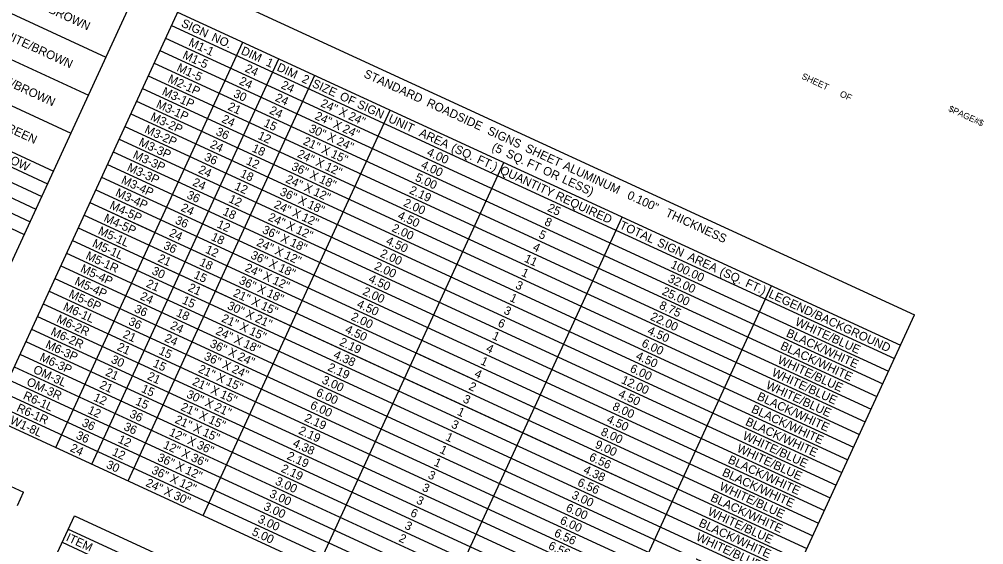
# Model space of a CAD drawing. Extents: x 627405 to 651306, y 367647 to 373430.
# Drawn here: x 650630 to 651306, y 372714 to 373082 of the extents above; entities that cross this region are included whole.
import ezdxf

# ---------------------------------------------------------------- set-up
doc = ezdxf.new("R2010")
doc.units = 0
for name, color, linetype in [('Default', 7, 'Continuous'), ('R_Border', 7, 'Continuous'), ('R_Dimension', 7, 'Continuous'), ('R_No Plot', 7, 'Continuous')]:
    doc.layers.add(name, color=color, linetype=linetype)

msp = doc.modelspace()

# ---------------------------------------------------------------- linework, layer by layer
at = {"layer": 'Default'}
for p, q in [((650174.87, 373293.17), (650691.12, 373055.28)), ((650162.63, 373266.61), (650678.88, 373028.72)), ((650150.38, 373240.04), (650666.63, 373002.15)), ((650138.14, 373213.48), (650654.39, 372975.59)), ((650134.06, 373204.62), (650650.31, 372966.73)), ((650129.98, 373195.77), (650646.23, 372957.88)), ((650125.9, 373186.91), (650642.15, 372949.02)), ((650581.15, 372816.64), (650754.16, 373192.09)), ((650121.82, 373178.06), (650638.07, 372940.17)), ((650117.74, 373169.2), (650633.99, 372931.31)), ((650610.54, 372803.1), (650751.11, 373108.15)), ((650751.11, 373108.15), (651257.18, 372874.95)), ((650741.32, 373086.9), (651247.38, 372853.7)), ((650737.03, 373077.6), (651243.1, 372844.4)), ((650656.14, 372782.08), (650786.92, 373065.89)), ((650732.95, 373068.75), (651239.02, 372835.55)), ((650728.87, 373059.89), (651234.94, 372826.69)), ((650681.38, 372770.45), (650812.16, 373054.26)), ((650724.79, 373051.04), (651230.86, 372817.84)), ((650706.62, 372758.82), (650837.39, 373042.63)), ((650720.71, 373042.18), (651226.78, 372808.98)), ((650716.63, 373033.33), (651222.7, 372800.13)), ((650049.03, 373020.09), (650633.46, 372750.78)), ((650712.55, 373024.47), (651218.62, 372791.27)), ((650759.3, 372734.54), (650890.08, 373018.35)), ((650564.07, 373017.21), (650654.39, 372975.59)), ((650708.47, 373015.62), (651214.54, 372782.42)), ((650559.99, 373008.35), (650650.31, 372966.73)), ((650704.39, 373006.76), (651210.46, 372773.56)), ((650555.91, 372999.5), (650646.23, 372957.88)), ((650700.31, 372997.91), (651206.38, 372764.71)), ((650551.83, 372990.64), (650642.15, 372949.02)), ((650696.23, 372989.05), (651202.29, 372755.85)), ((650547.75, 372981.79), (650638.07, 372940.17)), ((650692.15, 372980.2), (651198.21, 372747)), ((650839, 372697.82), (650969.78, 372981.62)), ((650543.67, 372972.93), (650633.99, 372931.31)), ((650688.07, 372971.34), (651194.13, 372738.14)), ((650683.99, 372962.49), (651190.05, 372729.29)), ((650679.91, 372953.63), (650725.51, 372932.62)), ((650679.91, 372953.63), (651185.97, 372720.43)), ((650675.83, 372944.78), (651181.89, 372711.58)), ((650675.83, 372944.78), (651181.89, 372711.58)), ((650921.79, 372659.67), (651052.57, 372943.47)), ((650671.75, 372935.92), (651087.49, 372744.34)), ((650671.75, 372935.92), (650983, 372792.49)), ((650667.66, 372927.07), (651173.73, 372693.87)), ((650663.58, 372918.21), (651169.65, 372685.01)), ((650659.5, 372909.36), (651165.57, 372676.16)), ((650655.42, 372900.5), (651161.49, 372667.3)), ((650651.34, 372891.65), (651157.41, 372658.45)), ((651026.28, 372611.52), (651157.06, 372895.32)), ((650647.26, 372882.79), (651153.33, 372649.59)), ((650643.18, 372873.94), (651149.25, 372640.74)), ((651116.6, 372569.9), (651257.18, 372874.95)), ((650639.1, 372865.08), (651145.17, 372631.88)), ((650635.02, 372856.23), (651141.09, 372623.03)), ((650630.94, 372847.37), (651137.01, 372614.17)), ((650908.37, 372848.36), (650991.16, 372810.2)), ((650626.86, 372838.52), (651132.93, 372605.32)), ((650622.78, 372829.66), (651128.85, 372596.46)), ((650618.7, 372820.81), (651124.77, 372587.61)), ((650614.62, 372811.95), (651120.69, 372578.75)), ((650991.16, 372810.2), (651185.97, 372720.43)), ((650610.54, 372803.1), (650839, 372697.82)), ((650983, 372792.49), (651177.81, 372702.72)), ((650629.18, 372741.48), (650633.46, 372750.78)), ((650603.15, 372591.37), (650669.05, 372734.38)), ((650669.05, 372734.38), (651103.39, 372534.24)), ((650664.77, 372725.09), (651099.11, 372524.94)), ((650660.48, 372715.79), (651094.82, 372515.64)), ((650847.16, 372715.53), (650929.95, 372677.38))]:
    msp.add_line(p, q, dxfattribs=at)
at = {"layer": 'R_Dimension'}
msp.add_line((650669.05, 372734.38), (650669.05, 372734.38), dxfattribs=at)

# ---------------------------------------------------------------- texts
at = {"layer": 'Default'}
for s, p in [('WHITE/BROWN', (650625, 373098.55)), ('SIGN', (650743.35, 373077.02)), ('WHITE/BROWN', (650612.76, 373071.98)), (' NO.', (650762.53, 373068.18)), ('M1-1', (650748.5, 373063.65)), ('M1-5', (650744.32, 373054.84)), ('DIM', (650785.17, 373057.75)), (' 1', (650800.6, 373050.64)), ('WHITE/BROWN', (650600.52, 373045.42)), ('M1-5', (650740.24, 373045.99)), ('24', (650787.96, 373045.46)), ('DIM', (650810.29, 373046.18)), ('STANDARD', (650871.14, 373041.61)), ('M2-1P', (650733.96, 373038.14)), ('24', (650783.88, 373036.61)), ('24', (650813.2, 373033.83)), (' 2', (650825.72, 373039.07)), ('SIZE', (650834.92, 373034.83)), ('M3-1P', (650729.88, 373029.29)), ('30', (650779.86, 373027.73)), ('M3-1P', (650725.8, 373020.43)), ('24', (650809.12, 373024.98)), ('24"', (650840.89, 373021.07)), (' OF', (650852.2, 373026.86)), (' SIGN', (650864.38, 373021.25)), (' ROADSIDE', (650913.06, 373022.29)), ('WHITE/GREEN', (650589.81, 373018.15)), ('21', (650775.93, 373018.8)), ('24', (650805.04, 373016.12)), (' X', (650851.66, 373016.11)), ('M3-2P', (650721.72, 373011.58)), ('24', (650771.64, 373010.04)), ('15', (650801.06, 373007.22)), ('24"', (650836.81, 373012.22)), (' X', (650847.58, 373007.26)), (' 24"', (650858.32, 373013.04)), ('UNIT', (650888.3, 373010.23)), ('BLACK/YELLOW', (650579.76, 373001.31)), ('M3-2P', (650717.64, 373002.72)), ('36', (650767.59, 373001.17)), ('30"', (650832.73, 373003.36)), (' 24"', (650854.24, 373004.19)), (' AREA', (650907.83, 373001.23)), (' SIGNS', (650955.56, 373002.71)), ('M3-3P', (650713.56, 372993.87)), ('12', (650796.95, 372998.38)), ('21"', (650828.65, 372994.51)), (' X', (650843.5, 372998.4)), (' 24"', (650850.16, 372995.33)), ('24', (650763.48, 372992.33)), ('18', (650792.84, 372989.54)), (' X', (650839.42, 372989.55)), ('4.00', (650915.23, 372986.82)), (' (SQ.', (650930.36, 372990.85)), ('(5', (650960.78, 372990.39)), (' SHEET', (650982.09, 372990.48)), ('M3-3P', (650709.48, 372985.01)), ('36', (650759.43, 372983.46)), ('12', (650788.79, 372980.67)), ('24"', (650824.57, 372985.65)), (' X', (650835.34, 372980.69)), (' 15"', (650846.08, 372986.48)), (' FT.)', (650948.29, 372982.59)), (' SQ.', (650968.62, 372986.78)), (' FT', (650983.15, 372980.09)), ('M3-3P', (650705.4, 372976.16)), ('24', (650755.32, 372974.62)), ('36"', (650820.49, 372976.8)), (' 12"', (650842, 372977.62)), ('4.00', (650911.15, 372977.96)), ('QUANTITY REQUIRED', (650966.43, 372974.23)), (' OR', (650994.29, 372974.95)), (' ALUMINUM', (651008.58, 372978.28)), ('M3-4P', (650701.32, 372967.3)), ('24', (650751.24, 372965.77)), ('18', (650784.68, 372971.83)), ('24"', (650816.41, 372967.94)), (' X', (650831.26, 372971.84)), (' 18"', (650837.92, 372968.77)), ('5.00', (650907.07, 372969.11)), (' LESS)', (651007.86, 372968.7)), ('12', (650780.63, 372962.96)), ('36"', (650812.32, 372959.09)), (' X', (650827.18, 372962.98)), ('2.19', (650902.99, 372960.25)), ('M3-4P', (650697.24, 372958.45)), ('36', (650747.19, 372956.9)), ('12', (650776.55, 372954.1)), (' X', (650823.1, 372954.13)), (' 12"', (650833.83, 372959.91)), (' 0.100"', (651053.49, 372957.58)), ('M4-5P', (650693.16, 372949.59)), ('24', (650743.08, 372948.06)), ('24"', (650808.24, 372950.23)), (' 18"', (650829.75, 372951.06)), ('2.00', (650898.91, 372951.4)), ('25', (650999.7, 372947.89)), ('M4-5P', (650689.08, 372940.73)), ('36', (650739.03, 372939.19)), ('18', (650772.44, 372945.26)), ('24"', (650804.16, 372941.38)), (' X', (650819.01, 372945.27)), (' 12"', (650825.67, 372942.2)), ('4.50', (650894.83, 372942.54)), (' THICKNESS', (651080.31, 372945.22)), ('M5-1L', (650685.14, 372931.81)), ('12', (650768.39, 372936.39)), ('36"', (650800.08, 372932.52)), (' X', (650814.93, 372936.42)), (' 12"', (650821.59, 372933.35)), ('2.00', (650890.75, 372933.69)), ('8', (650997.6, 372938.12)), ('TOTAL', (651050.12, 372935.66)), ('24', (650734.92, 372930.35)), ('18', (650764.28, 372927.55)), (' X', (650810.85, 372927.56)), ('5', (650993.58, 372929.24)), ('M5-1L', (650681.06, 372922.96)), ('36', (650730.87, 372921.48)), ('24"', (650796, 372923.67)), (' 18"', (650817.51, 372924.49)), ('4.50', (650886.67, 372924.83)), ('4', (650989.4, 372920.43)), (' SIGN', (651074.4, 372924.47)), ('M5-1R', (650676.45, 372914.35)), ('21', (650726.97, 372912.54)), ('12', (650760.23, 372918.68)), ('36"', (650791.92, 372914.81)), (' X', (650806.77, 372918.71)), (' 12"', (650813.43, 372915.64)), ('2.00', (650882.59, 372915.98)), ('11', (650983.49, 372912.42)), (' AREA', (651095.78, 372914.62)), ('M5-4P', (650672.75, 372905.31)), ('18', (650756.11, 372909.84)), ('24"', (650787.84, 372905.96)), (' X', (650802.69, 372909.85)), (' 18"', (650809.35, 372906.78)), ('2.00', (650878.51, 372907.12)), ('100.00', (651086.03, 372908.11)), ('30', (650722.73, 372903.76)), ('15', (650752.09, 372900.96)), (' X', (650798.61, 372901)), ('1', (650981.45, 372902.62)), ('32.00', (651083.99, 372898.31)), (' (SQ.', (651118.31, 372904.24)), ('M5-4P', (650668.67, 372896.46)), ('21', (650718.8, 372894.83)), ('21', (650748.12, 372892.06)), ('36"', (650783.76, 372897.1)), (' X', (650794.53, 372892.14)), (' 12"', (650805.27, 372897.93)), ('4.50', (650874.43, 372898.27)), ('3', (650977.28, 372893.81)), (' FT.)', (651136.24, 372895.98)), ('M5-6P', (650664.59, 372887.6)), ('24', (650714.51, 372886.07)), ('21"', (650779.68, 372888.25)), (' 18"', (650801.19, 372889.07)), ('2.00', (650870.35, 372889.41)), ('25.00', (651079.91, 372889.46)), ('LEGEND/BACKGROUND', (651154.55, 372887.54)), ('M6-1L', (650660.66, 372878.68)), ('15', (650743.93, 372883.25)), ('30"', (650775.6, 372879.39)), (' X', (650790.45, 372883.29)), (' 15"', (650797.11, 372880.22)), ('4.50', (650866.27, 372880.56)), ('1', (650973.29, 372884.91)), ('8.75', (651077.92, 372879.64)), ('36', (650710.46, 372877.2)), ('18', (650739.79, 372874.42)), (' X', (650786.37, 372874.43)), ('2.00', (650862.19, 372871.7)), ('3', (650969.12, 372876.1)), ('22.00', (651071.75, 372871.75)), ('M6-2R', (650656.05, 372870.07)), ('36', (650706.38, 372868.35)), ('24', (650735.67, 372865.59)), ('21"', (650771.52, 372870.54)), (' X', (650782.29, 372865.58)), (' 21"', (650793.03, 372871.36)), ('6', (650964.95, 372867.29)), ('WHITE/BLUE', (651173.1, 372867.99)), ('M6-2R', (650651.97, 372861.22)), ('21', (650702.48, 372859.41)), ('24"', (650767.44, 372861.68)), (' 15"', (650788.95, 372862.51)), ('4.50', (650858.1, 372862.85)), ('1', (650961.05, 372858.35)), ('4.50', (651069.72, 372861.95)), ('BLACK/WHITE', (651166.88, 372860.12)), ('M6-3P', (650648.27, 372852.18)), ('24', (650731.59, 372856.73)), ('36"', (650763.36, 372852.83)), (' X', (650778.21, 372856.72)), (' 18"', (650784.87, 372853.65)), ('2.19', (650854.03, 372853.99)), ('6.00', (651065.64, 372853.1)), ('BLACK/WHITE', (651162.8, 372851.26)), ('21', (650698.4, 372850.55)), ('15', (650727.61, 372847.83)), (' X', (650774.13, 372847.87)), ('4.38', (650849.93, 372845.14)), ('4', (650956.76, 372849.59)), ('M6-3P', (650644.19, 372843.33)), ('30', (650694.17, 372841.77)), ('15', (650723.53, 372838.98)), ('36"', (650759.28, 372843.97)), (' X', (650770.05, 372839.01)), (' 24"', (650780.79, 372844.8)), ('1', (650952.89, 372840.64)), ('4.50', (651061.56, 372844.24)), ('WHITE/BLUE', (651160.86, 372841.42)), ('OM-3L', (650639.65, 372834.69)), ('21', (650690.24, 372832.84)), ('21"', (650755.2, 372835.12)), (' 24"', (650776.71, 372835.94)), ('2.19', (650845.87, 372836.28)), ('4', (650948.6, 372831.88)), ('6.00', (651057.48, 372835.39)), ('WHITE/BLUE', (651156.78, 372832.57)), ('OM-3R', (650635.04, 372826.08)), ('21', (650686.16, 372823.99)), ('21', (650719.56, 372830.07)), ('21"', (650751.12, 372826.26)), (' X', (650765.97, 372830.15)), (' 15"', (650772.63, 372827.09)), ('3.00', (650841.78, 372827.43)), ('12.00', (651051.35, 372827.47)), ('WHITE/BLUE', (651152.7, 372823.71)), ('15', (650715.37, 372821.27)), ('30"', (650747.04, 372817.41)), (' X', (650761.89, 372821.3)), ('6.00', (650837.7, 372818.57)), ('2', (650944.59, 372822.99)), ('R6-1L', (650632.66, 372816.44)), ('12', (650681.94, 372815.2)), ('15', (650711.29, 372812.41)), (' X', (650757.81, 372812.44)), (' 15"', (650768.55, 372818.23)), ('3', (650940.56, 372814.12)), ('4.50', (651049.31, 372817.68)), ('BLACK/WHITE', (651146.48, 372815.84)), ('R6-1R', (650628.05, 372807.83)), ('12', (650677.86, 372806.34)), ('21"', (650742.96, 372808.55)), (' 21"', (650764.47, 372809.38)), ('6.00', (650833.62, 372809.71)), ('1', (650936.57, 372805.22)), ('8.00', (651045.23, 372808.82)), ('BLACK/WHITE', (651142.4, 372806.99)), ('W1-8L', (650623.44, 372799.21)), ('36', (650673.74, 372797.51)), ('36', (650707.14, 372803.59)), ('21"', (650738.88, 372799.7)), (' X', (650753.73, 372803.59)), (' 15"', (650760.39, 372800.52)), ('2.19', (650829.55, 372800.86)), ('4.50', (651041.15, 372799.97)), ('BLACK/WHITE', (651138.32, 372798.13)), ('36', (650703.06, 372794.73)), ('12"', (650734.8, 372790.84)), (' X', (650749.65, 372794.73)), (' 15"', (650756.31, 372791.67)), ('2.19', (650825.47, 372792)), ('3', (650932.39, 372796.41)), ('8.00', (651037.07, 372791.11)), ('36', (650669.66, 372788.65)), ('12', (650699.02, 372785.86)), (' X', (650745.57, 372785.88)), ('1', (650928.4, 372787.51)), ('WHITE/BLUE', (651136.38, 372788.29)), ('24', (650665.55, 372779.81)), ('12"', (650730.71, 372781.99)), (' 36"', (650752.23, 372782.81)), ('4.38', (650821.36, 372783.16)), ('1', (650924.32, 372778.65)), ('9.00', (651032.99, 372782.26)), ('WHITE/BLUE', (651132.3, 372779.44)), ('12', (650694.94, 372777)), ('36"', (650726.63, 372773.13)), (' X', (650741.49, 372777.02)), (' 36"', (650748.14, 372773.96)), ('2.19', (650817.3, 372774.29)), ('6.56', (651028.89, 372773.41)), ('BLACK/WHITE', (651126.08, 372771.57)), ('30', (650690.84, 372768.16)), ('36"', (650722.55, 372764.28)), (' X', (650737.4, 372768.17)), (' 12"', (650744.06, 372765.1)), ('2.19', (650813.22, 372765.44)), ('1', (650920.24, 372769.8)), ('4.38', (651024.82, 372764.55)), (' X', (650733.32, 372759.31)), ('3.00', (650809.14, 372756.58)), ('3', (650916.07, 372760.99)), ('BLACK/WHITE', (651122, 372762.71)), ('24"', (650718.47, 372755.42)), (' X', (650729.24, 372750.46)), (' 12"', (650739.98, 372756.25)), ('3', (650911.99, 372752.13)), ('6.56', (651020.72, 372755.7)), ('WHITE/BLUE', (651120.06, 372752.87)), (' 30"', (650735.9, 372747.39)), ('3.00', (650805.06, 372747.73)), ('3', (650907.91, 372743.28)), ('3.00', (651016.67, 372746.84)), ('BLACK/WHITE', (651113.84, 372745)), ('3.00', (650800.98, 372738.87)), ('6.00', (651012.59, 372737.98)), ('3.00', (650796.9, 372730.02)), ('6', (650903.74, 372734.46)), ('WHITE/BLUE', (651111.9, 372735.16)), ('3', (650899.75, 372725.57)), ('6.00', (651008.51, 372729.13)), ('BLACK/WHITE', (651105.67, 372727.29)), ('ITEM', (650662.68, 372717.11)), ('5.00', (650792.82, 372721.16)), ('2', (650895.62, 372716.73)), ('6.56', (651004.4, 372720.28)), ('WHITE/BLUE', (651103.74, 372717.45)), ('6.56', (651000.32, 372711.43))]:
    msp.add_text(s, height=6, rotation=335.25934, dxfattribs=at).set_placement(p)
at = {"layer": 'R_Border'}
msp.add_text('$PAGE#$', height=4.396, rotation=335.25934, dxfattribs=at).set_placement((651280.59, 373017.74))
at = {"layer": 'R_No Plot'}
for s, p in [('SHEET', (651177.7, 373040.38)), ('OF', (651204.45, 373028.05))]:
    msp.add_text(s, height=4.5, rotation=335.25934, dxfattribs=at).set_placement(p)

doc.saveas('drawing.dxf')
